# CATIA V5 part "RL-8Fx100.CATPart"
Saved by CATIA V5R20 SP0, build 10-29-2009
Part number: _RL-8Fx100
Definition: NONE
Nomenclature: _RL-8Fx100
Source: Unknown
Description: PART-_RL-8Fx100-DESC
Bounding box of the stored display mesh (mm): x -100 to 9.5, y -4.8 to 4.8, z -4.8 to 4.8
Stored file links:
  C:\Users\Utente\Desktop\IO LAVORO\3D X SITO CF\X SITO\PLASTICA\RLF\RL-8Fx100.CATPart
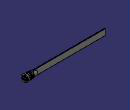
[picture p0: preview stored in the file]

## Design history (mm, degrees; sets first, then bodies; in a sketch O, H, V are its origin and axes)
Body1 "_RL-8Fx100" (main body)
  Solid1: solid without history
